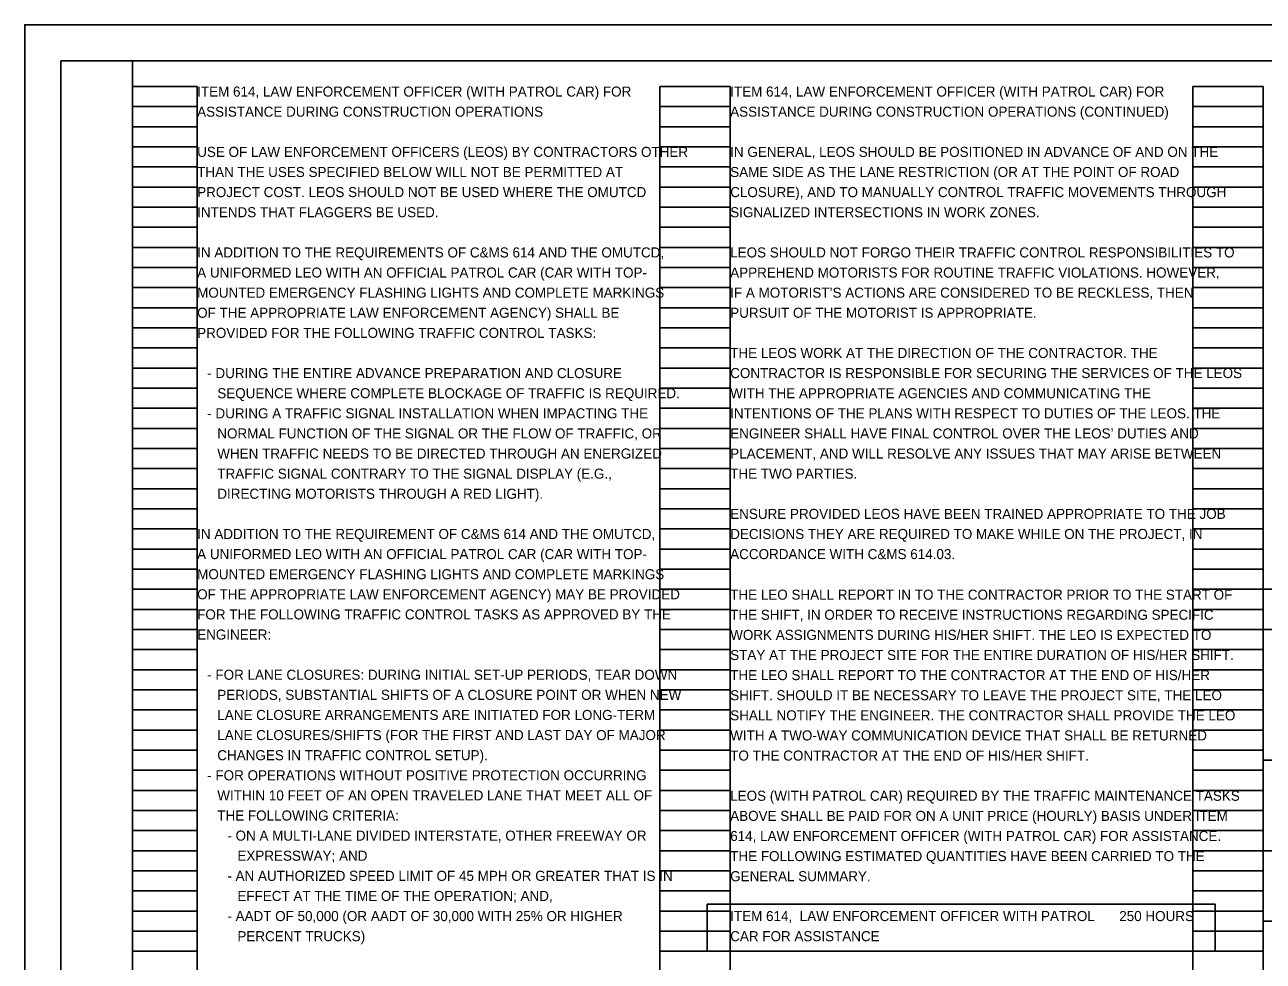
# Model space of a CAD drawing. Extents: x 0 to 52.3, y 0 to 22.
# Drawn here: x 0 to 17.24, y 8.96 to 22 of the extents above; entities that cross this region are included whole.
import ezdxf

# ---------------------------------------------------------------- set-up
doc = ezdxf.new("R2010")
doc.units = 0
for name, color, linetype in [('SC_Scratch1', 7, 'Continuous'), ('SH_Border', 7, 'Continuous'), ('SH_Cut_Line', 7, 'Continuous'), ('SH_Data', 7, 'Continuous'), ('SH_Text', 7, 'Continuous')]:
    doc.layers.add(name, color=color, linetype=linetype)

msp = doc.modelspace()

# ---------------------------------------------------------------- linework, layer by layer
at = {"layer": 'SC_Scratch1'}
msp.add_lwpolyline([(9.498, 9.757), (16.57, 9.757), (16.57, 9.1), (9.498, 9.1)], close=True, dxfattribs=at)
at = {"layer": 'SH_Border'}
for points in [[(0.5, 21.5), (1.5, 21.5), (1.5, 0.5), (0.5, 0.5)], [(1.5, 21.5), (33.5, 21.5), (33.5, 0.5), (1.5, 0.5)]]:
    msp.add_lwpolyline(points, close=True, dxfattribs=at)
at = {"layer": 'SH_Cut_Line'}
msp.add_lwpolyline([(0, 0), (34, 0), (34, 22), (0, 22)], close=True, dxfattribs=at)
at = {"layer": 'SH_Data'}
for p, q in [((1.5, 0.98), (1.5, 21.14)), ((1.5, 21.14), (2.4, 21.14)), ((2.4, 0.98), (2.4, 21.14)), ((8.84, 0.98), (8.84, 21.14)), ((8.84, 21.14), (9.82, 21.14)), ((9.82, 0.98), (9.82, 21.14)), ((16.26, 0.98), (16.26, 21.14)), ((16.26, 21.14), (17.24, 21.14)), ((17.24, 0.98), (17.24, 21.14)), ((1.5, 20.86), (2.4, 20.86)), ((8.84, 20.86), (9.82, 20.86)), ((16.26, 20.86), (17.24, 20.86)), ((1.5, 20.58), (2.4, 20.58)), ((8.84, 20.58), (9.82, 20.58)), ((16.26, 20.58), (17.24, 20.58)), ((1.5, 20.3), (2.4, 20.3)), ((8.84, 20.3), (9.82, 20.3)), ((16.26, 20.3), (17.24, 20.3)), ((1.5, 20.02), (2.4, 20.02)), ((8.84, 20.02), (9.82, 20.02)), ((16.26, 20.02), (17.24, 20.02)), ((1.5, 19.74), (2.4, 19.74)), ((8.84, 19.74), (9.82, 19.74)), ((16.26, 19.74), (17.24, 19.74)), ((1.5, 19.46), (2.4, 19.46)), ((8.84, 19.46), (9.82, 19.46)), ((16.26, 19.46), (17.24, 19.46)), ((1.5, 19.18), (2.4, 19.18)), ((8.84, 19.18), (9.82, 19.18)), ((16.26, 19.18), (17.24, 19.18)), ((1.5, 18.9), (2.4, 18.9)), ((8.84, 18.9), (9.82, 18.9)), ((16.26, 18.9), (17.24, 18.9)), ((1.5, 18.62), (2.4, 18.62)), ((8.84, 18.62), (9.82, 18.62)), ((16.26, 18.62), (17.24, 18.62)), ((1.5, 18.34), (2.4, 18.34)), ((8.84, 18.34), (9.82, 18.34)), ((16.26, 18.34), (17.24, 18.34)), ((1.5, 18.06), (2.4, 18.06)), ((8.84, 18.06), (9.82, 18.06)), ((16.26, 18.06), (17.24, 18.06)), ((1.5, 17.78), (2.4, 17.78)), ((8.84, 17.78), (9.82, 17.78)), ((16.26, 17.78), (17.24, 17.78)), ((1.5, 17.5), (2.4, 17.5)), ((8.84, 17.5), (9.82, 17.5)), ((16.26, 17.5), (17.24, 17.5)), ((1.5, 17.22), (2.4, 17.22)), ((8.84, 17.22), (9.82, 17.22)), ((16.26, 17.22), (17.24, 17.22)), ((1.5, 16.94), (2.4, 16.94)), ((8.84, 16.94), (9.82, 16.94)), ((16.26, 16.94), (17.24, 16.94)), ((1.5, 16.66), (2.4, 16.66)), ((8.84, 16.66), (9.82, 16.66)), ((16.26, 16.66), (17.24, 16.66)), ((1.5, 16.38), (2.4, 16.38)), ((8.84, 16.38), (9.82, 16.38)), ((16.26, 16.38), (17.24, 16.38)), ((1.5, 16.1), (2.4, 16.1)), ((8.84, 16.1), (9.82, 16.1)), ((16.26, 16.1), (17.24, 16.1)), ((1.5, 15.82), (2.4, 15.82)), ((8.84, 15.82), (9.82, 15.82)), ((16.26, 15.82), (17.24, 15.82)), ((1.5, 15.54), (2.4, 15.54)), ((8.84, 15.54), (9.82, 15.54)), ((16.26, 15.54), (17.24, 15.54)), ((1.5, 15.26), (2.4, 15.26)), ((8.84, 15.26), (9.82, 15.26)), ((16.26, 15.26), (17.24, 15.26)), ((1.5, 14.98), (2.4, 14.98)), ((8.84, 14.98), (9.82, 14.98)), ((16.26, 14.98), (17.24, 14.98)), ((1.5, 14.7), (2.4, 14.7)), ((8.84, 14.7), (9.82, 14.7)), ((16.26, 14.7), (17.24, 14.7)), ((1.5, 14.42), (2.4, 14.42)), ((8.84, 14.42), (9.82, 14.42)), ((16.26, 14.42), (17.24, 14.42)), ((1.5, 14.14), (2.4, 14.14)), ((8.84, 14.14), (9.82, 14.14)), ((16.26, 14.14), (17.24, 14.14)), ((1.5, 13.86), (2.4, 13.86)), ((8.84, 13.86), (9.82, 13.86)), ((16.26, 13.86), (17.24, 13.86)), ((1.5, 13.58), (2.4, 13.58)), ((8.84, 13.58), (9.82, 13.58)), ((16.26, 13.58), (17.24, 13.58)), ((1.5, 13.3), (2.4, 13.3)), ((8.84, 13.3), (9.82, 13.3)), ((16.26, 13.3), (17.24, 13.3)), ((1.5, 13.02), (2.4, 13.02)), ((8.84, 13.02), (9.82, 13.02)), ((16.26, 13.02), (17.24, 13.02)), ((1.5, 12.74), (2.4, 12.74)), ((8.84, 12.74), (9.82, 12.74)), ((16.26, 12.74), (17.24, 12.74)), ((1.5, 12.46), (2.4, 12.46)), ((8.84, 12.46), (9.82, 12.46)), ((16.26, 12.46), (17.24, 12.46)), ((1.5, 12.18), (2.4, 12.18)), ((8.84, 12.18), (9.82, 12.18)), ((16.26, 12.18), (17.24, 12.18)), ((1.5, 11.9), (2.4, 11.9)), ((8.84, 11.9), (9.82, 11.9)), ((16.26, 11.9), (17.24, 11.9)), ((1.5, 11.62), (2.4, 11.62)), ((8.84, 11.62), (9.82, 11.62)), ((16.26, 11.62), (17.24, 11.62)), ((1.5, 11.34), (2.4, 11.34)), ((8.84, 11.34), (9.82, 11.34)), ((16.26, 11.34), (17.24, 11.34)), ((1.5, 11.06), (2.4, 11.06)), ((8.84, 11.06), (9.82, 11.06)), ((16.26, 11.06), (17.24, 11.06)), ((1.5, 10.78), (2.4, 10.78)), ((8.84, 10.78), (9.82, 10.78)), ((16.26, 10.78), (17.24, 10.78)), ((1.5, 10.5), (2.4, 10.5)), ((8.84, 10.5), (9.82, 10.5)), ((16.26, 10.5), (17.24, 10.5)), ((1.5, 10.22), (2.4, 10.22)), ((8.84, 10.22), (9.82, 10.22)), ((16.26, 10.22), (17.24, 10.22)), ((1.5, 9.94), (2.4, 9.94)), ((8.84, 9.94), (9.82, 9.94)), ((16.26, 9.94), (17.24, 9.94)), ((1.5, 9.66), (2.4, 9.66)), ((8.84, 9.66), (9.82, 9.66)), ((16.26, 9.66), (17.24, 9.66)), ((1.5, 9.38), (2.4, 9.38)), ((8.84, 9.38), (9.82, 9.38)), ((16.26, 9.38), (17.24, 9.38)), ((1.5, 9.1), (2.4, 9.1)), ((8.84, 9.1), (9.82, 9.1)), ((16.26, 9.1), (17.24, 9.1))]:
    msp.add_line(p, q, dxfattribs=at)
at = {"layer": 'SH_Text'}
for p, q in [((17.24, 14.14), (24.378, 14.14)), ((17.24, 14.14), (17.24, 9.52)), ((17.24, 13.58), (24.378, 13.58)), ((24.378, 11.76), (17.24, 11.76)), ((24.378, 10.5), (17.24, 10.5)), ((24.378, 9.52), (17.24, 9.52))]:
    msp.add_line(p, q, dxfattribs=at)

# ---------------------------------------------------------------- texts
for s, p in [('ITEM 614, LAW ENFORCEMENT OFFICER (WITH PATROL CAR) FOR ', (2.4, 21)), ('ITEM 614, LAW ENFORCEMENT OFFICER (WITH PATROL CAR) FOR ', (9.82, 21)), ('ASSISTANCE DURING CONSTRUCTION OPERATIONS', (2.4, 20.72)), ('ASSISTANCE DURING CONSTRUCTION OPERATIONS (CONTINUED)', (9.82, 20.72)), ('USE OF LAW ENFORCEMENT OFFICERS (LEOS) BY CONTRACTORS OTHER ', (2.4, 20.16)), ('IN GENERAL, LEOS SHOULD BE POSITIONED IN ADVANCE OF AND ON THE ', (9.82, 20.16)), ('THAN THE USES SPECIFIED BELOW WILL NOT BE PERMITTED AT ', (2.4, 19.88)), ('SAME SIDE AS THE LANE RESTRICTION (OR AT THE POINT OF ROAD ', (9.82, 19.88)), ('PROJECT COST. LEOS SHOULD NOT BE USED WHERE THE OMUTCD ', (2.4, 19.6)), ('CLOSURE), AND TO MANUALLY CONTROL TRAFFIC MOVEMENTS THROUGH ', (9.82, 19.6)), ('INTENDS THAT FLAGGERS BE USED. ', (2.4, 19.32)), ('SIGNALIZED INTERSECTIONS IN WORK ZONES.', (9.82, 19.32)), ('IN ADDITION TO THE REQUIREMENTS OF C&MS 614 AND THE OMUTCD, ', (2.4, 18.76)), ('LEOS SHOULD NOT FORGO THEIR TRAFFIC CONTROL RESPONSIBILITIES TO ', (9.82, 18.76)), ('A UNIFORMED LEO WITH AN OFFICIAL PATROL CAR (CAR WITH TOP-', (2.4, 18.48)), ('APPREHEND MOTORISTS FOR ROUTINE TRAFFIC VIOLATIONS. HOWEVER, ', (9.82, 18.48)), ('MOUNTED EMERGENCY FLASHING LIGHTS AND COMPLETE MARKINGS ', (2.4, 18.2)), ('IF A MOTORIST’S ACTIONS ARE CONSIDERED TO BE RECKLESS, THEN ', (9.82, 18.2)), ('OF THE APPROPRIATE LAW ENFORCEMENT AGENCY) SHALL BE ', (2.4, 17.92)), ('PURSUIT OF THE MOTORIST IS APPROPRIATE.', (9.82, 17.92)), ('PROVIDED FOR THE FOLLOWING TRAFFIC CONTROL TASKS:', (2.4, 17.64)), ('THE LEOS WORK AT THE DIRECTION OF THE CONTRACTOR. THE ', (9.82, 17.36)), ('- DURING THE ENTIRE ADVANCE PREPARATION AND CLOSURE ', (2.54, 17.08)), ('CONTRACTOR IS RESPONSIBLE FOR SECURING THE SERVICES OF THE LEOS ', (9.82, 17.08)), ('SEQUENCE WHERE COMPLETE BLOCKAGE OF TRAFFIC IS REQUIRED.', (2.68, 16.8)), ('WITH THE APPROPRIATE AGENCIES AND COMMUNICATING THE ', (9.82, 16.8)), ('- DURING A TRAFFIC SIGNAL INSTALLATION WHEN IMPACTING THE ', (2.54, 16.52)), ('INTENTIONS OF THE PLANS WITH RESPECT TO DUTIES OF THE LEOS. THE ', (9.82, 16.52)), ('NORMAL FUNCTION OF THE SIGNAL OR THE FLOW OF TRAFFIC, OR ', (2.68, 16.24)), ('ENGINEER SHALL HAVE FINAL CONTROL OVER THE LEOS’ DUTIES AND ', (9.82, 16.24)), ('WHEN TRAFFIC NEEDS TO BE DIRECTED THROUGH AN ENERGIZED ', (2.68, 15.96)), ('PLACEMENT, AND WILL RESOLVE ANY ISSUES THAT MAY ARISE BETWEEN ', (9.82, 15.96)), ('TRAFFIC SIGNAL CONTRARY TO THE SIGNAL DISPLAY (E.G., ', (2.68, 15.68)), ('THE TWO PARTIES. ', (9.82, 15.68)), ('DIRECTING MOTORISTS THROUGH A RED LIGHT).', (2.68, 15.4)), ('ENSURE PROVIDED LEOS HAVE BEEN TRAINED APPROPRIATE TO THE JOB ', (9.82, 15.12)), ('IN ADDITION TO THE REQUIREMENT OF C&MS 614 AND THE OMUTCD, ', (2.4, 14.84)), ('DECISIONS THEY ARE REQUIRED TO MAKE WHILE ON THE PROJECT, IN ', (9.82, 14.84)), ('A UNIFORMED LEO WITH AN OFFICIAL PATROL CAR (CAR WITH TOP-', (2.4, 14.56)), ('ACCORDANCE WITH C&MS 614.03.', (9.82, 14.56)), ('MOUNTED EMERGENCY FLASHING LIGHTS AND COMPLETE MARKINGS ', (2.4, 14.28)), ('OF THE APPROPRIATE LAW ENFORCEMENT AGENCY) MAY BE PROVIDED ', (2.4, 14)), ('THE LEO SHALL REPORT IN TO THE CONTRACTOR PRIOR TO THE START OF ', (9.82, 13.995)), ('FOR THE FOLLOWING TRAFFIC CONTROL TASKS AS APPROVED BY THE ', (2.4, 13.72)), ('THE SHIFT, IN ORDER TO RECEIVE INSTRUCTIONS REGARDING SPECIFIC ', (9.82, 13.715)), ('ENGINEER:', (2.4, 13.44)), ('WORK ASSIGNMENTS DURING HIS/HER SHIFT. THE LEO IS EXPECTED TO ', (9.82, 13.435)), ('STAY AT THE PROJECT SITE FOR THE ENTIRE DURATION OF HIS/HER SHIFT. ', (9.82, 13.155)), ('- FOR LANE CLOSURES: DURING INITIAL SET-UP PERIODS, TEAR DOWN ', (2.54, 12.88)), ('THE LEO SHALL REPORT TO THE CONTRACTOR AT THE END OF HIS/HER ', (9.82, 12.875)), ('PERIODS, SUBSTANTIAL SHIFTS OF A CLOSURE POINT OR WHEN NEW ', (2.68, 12.6)), ('SHIFT. SHOULD IT BE NECESSARY TO LEAVE THE PROJECT SITE, THE LEO ', (9.82, 12.595)), ('LANE CLOSURE ARRANGEMENTS ARE INITIATED FOR LONG-TERM ', (2.68, 12.32)), ('SHALL NOTIFY THE ENGINEER. THE CONTRACTOR SHALL PROVIDE THE LEO ', (9.82, 12.315)), ('LANE CLOSURES/SHIFTS (FOR THE FIRST AND LAST DAY OF MAJOR ', (2.68, 12.04)), ('WITH A TWO-WAY COMMUNICATION DEVICE THAT SHALL BE RETURNED ', (9.82, 12.035)), ('CHANGES IN TRAFFIC CONTROL SETUP). ', (2.68, 11.76)), ('TO THE CONTRACTOR AT THE END OF HIS/HER SHIFT. ', (9.82, 11.755)), ('- FOR OPERATIONS WITHOUT POSITIVE PROTECTION OCCURRING ', (2.54, 11.48)), ('WITHIN 10 FEET OF AN OPEN TRAVELED LANE THAT MEET ALL OF ', (2.68, 11.2)), ('LEOS (WITH PATROL CAR) REQUIRED BY THE TRAFFIC MAINTENANCE TASKS ', (9.82, 11.195)), ('THE FOLLOWING CRITERIA: ', (2.68, 10.92)), ('ABOVE SHALL BE PAID FOR ON A UNIT PRICE (HOURLY) BASIS UNDER ITEM ', (9.82, 10.915)), ('- ON A MULTI-LANE DIVIDED INTERSTATE, OTHER FREEWAY OR ', (2.82, 10.64)), ('614, LAW ENFORCEMENT OFFICER (WITH PATROL CAR) FOR ASSISTANCE. ', (9.82, 10.635)), ('EXPRESSWAY; AND', (2.96, 10.36)), ('THE FOLLOWING ESTIMATED QUANTITIES HAVE BEEN CARRIED TO THE ', (9.82, 10.355)), ('- AN AUTHORIZED SPEED LIMIT OF 45 MPH OR GREATER THAT IS IN ', (2.82, 10.08)), ('GENERAL SUMMARY.', (9.82, 10.075)), ('EFFECT AT THE TIME OF THE OPERATION; AND,', (2.96, 9.8)), ('- AADT OF 50,000 (OR AADT OF 30,000 WITH 25% OR HIGHER ', (2.82, 9.52)), ('ITEM 614,  LAW ENFORCEMENT OFFICER WITH PATROL', (9.82, 9.52)), ('250 HOURS', (15.236, 9.52)), ('PERCENT TRUCKS)', (2.96, 9.24)), ('CAR FOR ASSISTANCE', (9.82, 9.24))]:
    msp.add_text(s, height=0.14, dxfattribs=at).set_placement(p)

doc.saveas('drawing.dxf')
